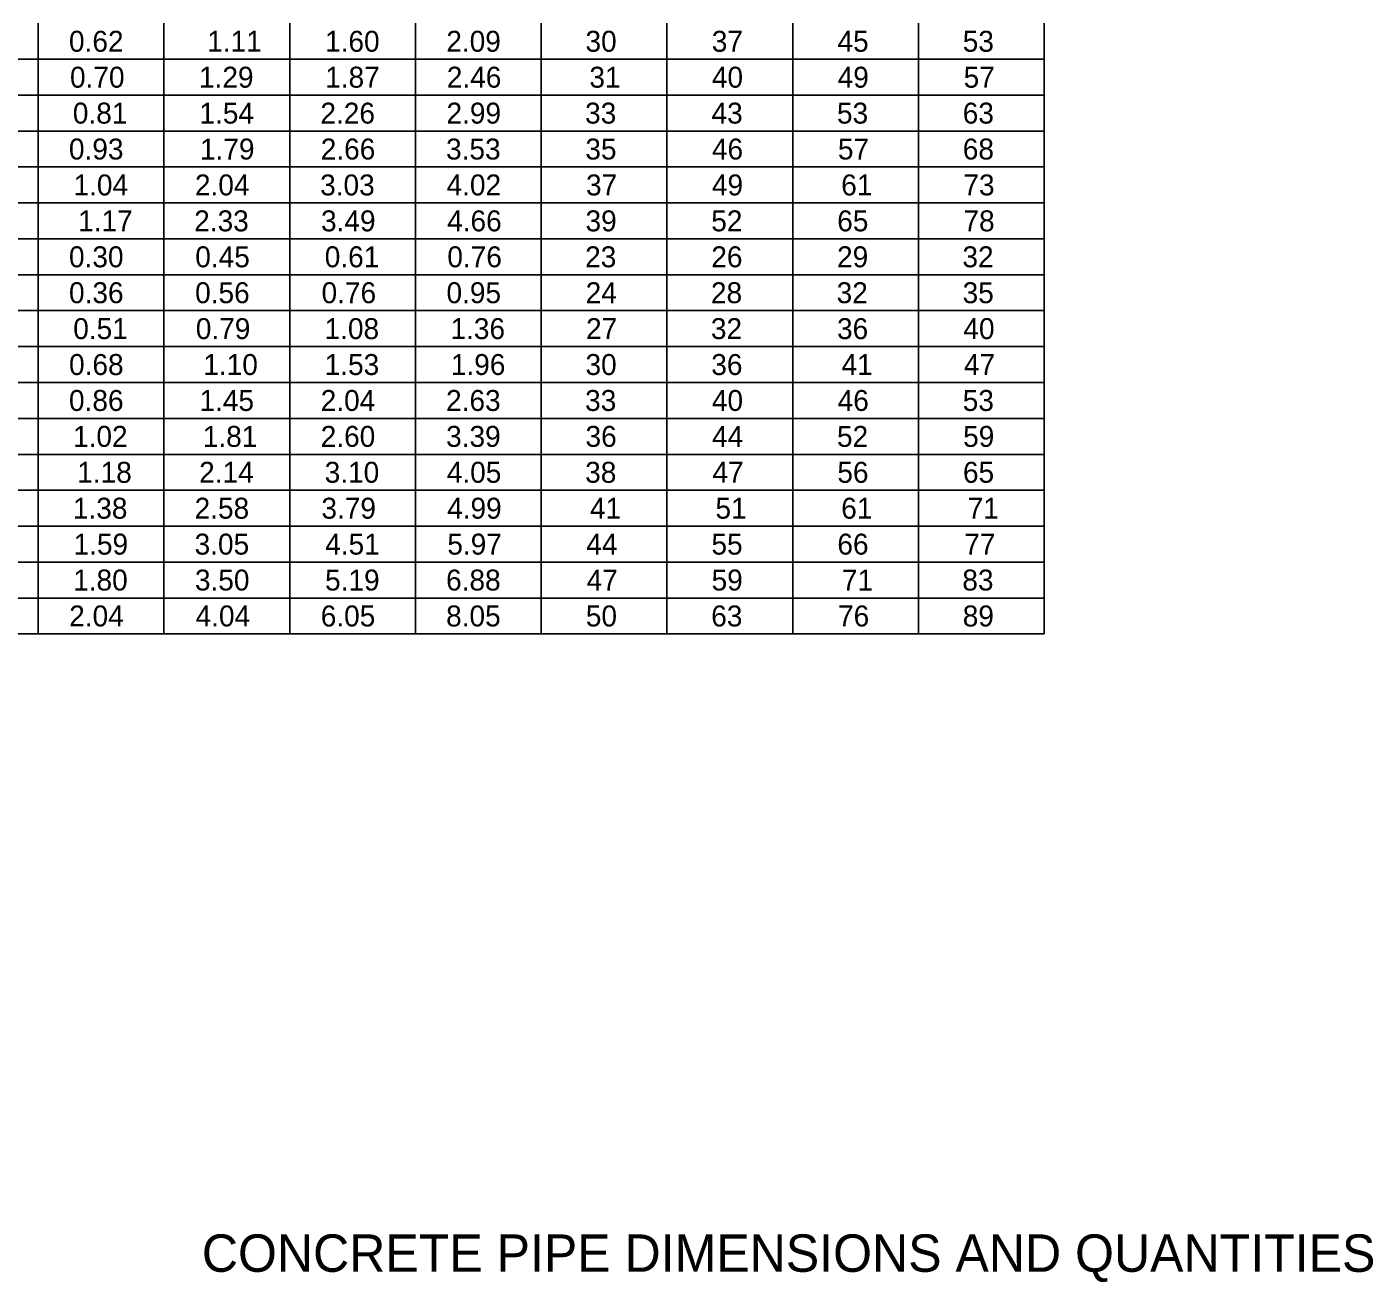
# Model space of a CAD drawing. Extents: x -1.3 to 14.6, y 0 to 8.4.
# Drawn here: x 10.062 to 14.558, y 0.024 to 4.218 of the extents above; entities that cross this region are included whole.
import ezdxf

# ---------------------------------------------------------------- set-up
doc = ezdxf.new("R2010")
doc.units = 0
doc.layers.add('Table', color=7, linetype='Continuous')
doc.layers.add('TextStructures', color=7, linetype='Continuous')

msp = doc.modelspace()

# ---------------------------------------------------------------- linework, layer by layer
at = {"layer": 'Table'}
for points in [[(10.1, 4.23), (10.1, 4.11), (10.1, 3.99), (10.1, 3.87), (10.1, 3.75), (10.1, 3.63), (10.1, 3.51), (10.1, 3.39), (10.1, 3.27), (10.1, 3.15), (10.1, 3.03), (10.1, 2.91), (10.1, 2.79), (10.1, 2.67), (10.1, 2.55), (10.1, 2.43), (10.1, 2.31), (10.1, 2.19)], [(10.52, 4.23), (10.52, 4.11), (10.52, 3.99), (10.52, 3.87), (10.52, 3.75), (10.52, 3.63), (10.52, 3.51), (10.52, 3.39), (10.52, 3.27), (10.52, 3.15), (10.52, 3.03), (10.52, 2.91), (10.52, 2.79), (10.52, 2.67), (10.52, 2.55), (10.52, 2.43), (10.52, 2.31), (10.52, 2.19)], [(10.94, 4.23), (10.94, 4.11), (10.94, 3.99), (10.94, 3.87), (10.94, 3.75), (10.94, 3.63), (10.94, 3.51), (10.94, 3.39), (10.94, 3.27), (10.94, 3.15), (10.94, 3.03), (10.94, 2.91), (10.94, 2.79), (10.94, 2.67), (10.94, 2.55), (10.94, 2.43), (10.94, 2.31), (10.94, 2.19)], [(11.36, 4.23), (11.36, 4.11), (11.36, 3.99), (11.36, 3.87), (11.36, 3.75), (11.36, 3.63), (11.36, 3.51), (11.36, 3.39), (11.36, 3.27), (11.36, 3.15), (11.36, 3.03), (11.36, 2.91), (11.36, 2.79), (11.36, 2.67), (11.36, 2.55), (11.36, 2.43), (11.36, 2.31), (11.36, 2.19)], [(11.78, 4.23), (11.78, 4.11), (11.78, 3.99), (11.78, 3.87), (11.78, 3.75), (11.78, 3.63), (11.78, 3.51), (11.78, 3.39), (11.78, 3.27), (11.78, 3.15), (11.78, 3.03), (11.78, 2.91), (11.78, 2.79), (11.78, 2.67), (11.78, 2.55), (11.78, 2.43), (11.78, 2.31), (11.78, 2.19)], [(12.2, 4.23), (12.2, 4.11), (12.2, 3.99), (12.2, 3.87), (12.2, 3.75), (12.2, 3.63), (12.2, 3.51), (12.2, 3.39), (12.2, 3.27), (12.2, 3.15), (12.2, 3.03), (12.2, 2.91), (12.2, 2.79), (12.2, 2.67), (12.2, 2.55), (12.2, 2.43), (12.2, 2.31), (12.2, 2.19)], [(12.62, 4.23), (12.62, 4.11), (12.62, 3.99), (12.62, 3.87), (12.62, 3.75), (12.62, 3.63), (12.62, 3.51), (12.62, 3.39), (12.62, 3.27), (12.62, 3.15), (12.62, 3.03), (12.62, 2.91), (12.62, 2.79), (12.62, 2.67), (12.62, 2.55), (12.62, 2.43), (12.62, 2.31), (12.62, 2.19)], [(13.04, 4.23), (13.04, 4.11), (13.04, 3.99), (13.04, 3.87), (13.04, 3.75), (13.04, 3.63), (13.04, 3.51), (13.04, 3.39), (13.04, 3.27), (13.04, 3.15), (13.04, 3.03), (13.04, 2.91), (13.04, 2.79), (13.04, 2.67), (13.04, 2.55), (13.04, 2.43), (13.04, 2.31), (13.04, 2.19)], [(13.46, 4.23), (13.46, 4.11), (13.46, 3.99), (13.46, 3.87), (13.46, 3.75), (13.46, 3.63), (13.46, 3.51), (13.46, 3.39), (13.46, 3.27), (13.46, 3.15), (13.46, 3.03), (13.46, 2.91), (13.46, 2.79), (13.46, 2.67), (13.46, 2.55), (13.46, 2.43), (13.46, 2.31), (13.46, 2.19)], [(4.04, 4.11), (4.52, 4.11), (4.94, 4.11), (5.42, 4.11), (5.66, 4.11), (6.02, 4.11), (6.38, 4.11), (6.8, 4.11), (7.22, 4.11), (7.64, 4.11), (8.06, 4.11), (8.42, 4.11), (8.84, 4.11), (9.26, 4.11), (9.68, 4.11), (10.1, 4.11), (10.52, 4.11), (10.94, 4.11), (11.36, 4.11), (11.78, 4.11), (12.2, 4.11), (12.62, 4.11), (13.04, 4.11), (13.46, 4.11)], [(4.04, 3.99), (4.52, 3.99), (4.94, 3.99), (5.42, 3.99), (5.66, 3.99), (6.02, 3.99), (6.38, 3.99), (6.8, 3.99), (7.22, 3.99), (7.64, 3.99), (8.06, 3.99), (8.42, 3.99), (8.84, 3.99), (9.26, 3.99), (9.68, 3.99), (10.1, 3.99), (10.52, 3.99), (10.94, 3.99), (11.36, 3.99), (11.78, 3.99), (12.2, 3.99), (12.62, 3.99), (13.04, 3.99), (13.46, 3.99)], [(4.04, 3.87), (4.52, 3.87), (4.94, 3.87), (5.42, 3.87), (5.66, 3.87), (6.02, 3.87), (6.38, 3.87), (6.8, 3.87), (7.22, 3.87), (7.64, 3.87), (8.06, 3.87), (8.42, 3.87), (8.84, 3.87), (9.26, 3.87), (9.68, 3.87), (10.1, 3.87), (10.52, 3.87), (10.94, 3.87), (11.36, 3.87), (11.78, 3.87), (12.2, 3.87), (12.62, 3.87), (13.04, 3.87), (13.46, 3.87)], [(4.04, 3.75), (4.52, 3.75), (4.94, 3.75), (5.42, 3.75), (5.66, 3.75), (6.02, 3.75), (6.38, 3.75), (6.8, 3.75), (7.22, 3.75), (7.64, 3.75), (8.06, 3.75), (8.42, 3.75), (8.84, 3.75), (9.26, 3.75), (9.68, 3.75), (10.1, 3.75), (10.52, 3.75), (10.94, 3.75), (11.36, 3.75), (11.78, 3.75), (12.2, 3.75), (12.62, 3.75), (13.04, 3.75), (13.46, 3.75)], [(4.04, 3.63), (4.52, 3.63), (4.94, 3.63), (5.42, 3.63), (5.66, 3.63), (6.02, 3.63), (6.38, 3.63), (6.8, 3.63), (7.22, 3.63), (7.64, 3.63), (8.06, 3.63), (8.42, 3.63), (8.84, 3.63), (9.26, 3.63), (9.68, 3.63), (10.1, 3.63), (10.52, 3.63), (10.94, 3.63), (11.36, 3.63), (11.78, 3.63), (12.2, 3.63), (12.62, 3.63), (13.04, 3.63), (13.46, 3.63)], [(4.04, 3.51), (4.52, 3.51), (4.94, 3.51), (5.42, 3.51), (5.66, 3.51), (6.02, 3.51), (6.38, 3.51), (6.8, 3.51), (7.22, 3.51), (7.64, 3.51), (8.06, 3.51), (8.42, 3.51), (8.84, 3.51), (9.26, 3.51), (9.68, 3.51), (10.1, 3.51), (10.52, 3.51), (10.94, 3.51), (11.36, 3.51), (11.78, 3.51), (12.2, 3.51), (12.62, 3.51), (13.04, 3.51), (13.46, 3.51)], [(4.04, 3.39), (4.52, 3.39), (4.94, 3.39), (5.42, 3.39), (5.66, 3.39), (6.02, 3.39), (6.38, 3.39), (6.8, 3.39), (7.22, 3.39), (7.64, 3.39), (8.06, 3.39), (8.42, 3.39), (8.84, 3.39), (9.26, 3.39), (9.68, 3.39), (10.1, 3.39), (10.52, 3.39), (10.94, 3.39), (11.36, 3.39), (11.78, 3.39), (12.2, 3.39), (12.62, 3.39), (13.04, 3.39), (13.46, 3.39)], [(4.04, 3.27), (4.52, 3.27), (4.94, 3.27), (5.42, 3.27), (5.66, 3.27), (6.02, 3.27), (6.38, 3.27), (6.8, 3.27), (7.22, 3.27), (7.64, 3.27), (8.06, 3.27), (8.42, 3.27), (8.84, 3.27), (9.26, 3.27), (9.68, 3.27), (10.1, 3.27), (10.52, 3.27), (10.94, 3.27), (11.36, 3.27), (11.78, 3.27), (12.2, 3.27), (12.62, 3.27), (13.04, 3.27), (13.46, 3.27)], [(4.04, 3.15), (4.52, 3.15), (4.94, 3.15), (5.42, 3.15), (5.66, 3.15), (6.02, 3.15), (6.38, 3.15), (6.8, 3.15), (7.22, 3.15), (7.64, 3.15), (8.06, 3.15), (8.42, 3.15), (8.84, 3.15), (9.26, 3.15), (9.68, 3.15), (10.1, 3.15), (10.52, 3.15), (10.94, 3.15), (11.36, 3.15), (11.78, 3.15), (12.2, 3.15), (12.62, 3.15), (13.04, 3.15), (13.46, 3.15)], [(4.04, 3.03), (4.52, 3.03), (4.94, 3.03), (5.42, 3.03), (5.66, 3.03), (6.02, 3.03), (6.38, 3.03), (6.8, 3.03), (7.22, 3.03), (7.64, 3.03), (8.06, 3.03), (8.42, 3.03), (8.84, 3.03), (9.26, 3.03), (9.68, 3.03), (10.1, 3.03), (10.52, 3.03), (10.94, 3.03), (11.36, 3.03), (11.78, 3.03), (12.2, 3.03), (12.62, 3.03), (13.04, 3.03), (13.46, 3.03)], [(4.04, 2.91), (4.52, 2.91), (4.94, 2.91), (5.42, 2.91), (5.66, 2.91), (6.02, 2.91), (6.38, 2.91), (6.8, 2.91), (7.22, 2.91), (7.64, 2.91), (8.06, 2.91), (8.42, 2.91), (8.84, 2.91), (9.26, 2.91), (9.68, 2.91), (10.1, 2.91), (10.52, 2.91), (10.94, 2.91), (11.36, 2.91), (11.78, 2.91), (12.2, 2.91), (12.62, 2.91), (13.04, 2.91), (13.46, 2.91)], [(4.04, 2.79), (4.52, 2.79), (4.94, 2.79), (5.42, 2.79), (5.66, 2.79), (6.02, 2.79), (6.38, 2.79), (6.8, 2.79), (7.22, 2.79), (7.64, 2.79), (8.06, 2.79), (8.42, 2.79), (8.84, 2.79), (9.26, 2.79), (9.68, 2.79), (10.1, 2.79), (10.52, 2.79), (10.94, 2.79), (11.36, 2.79), (11.78, 2.79), (12.2, 2.79), (12.62, 2.79), (13.04, 2.79), (13.46, 2.79)], [(4.04, 2.67), (4.52, 2.67), (4.94, 2.67), (5.42, 2.67), (5.66, 2.67), (6.02, 2.67), (6.38, 2.67), (6.8, 2.67), (7.22, 2.67), (7.64, 2.67), (8.06, 2.67), (8.42, 2.67), (8.84, 2.67), (9.26, 2.67), (9.68, 2.67), (10.1, 2.67), (10.52, 2.67), (10.94, 2.67), (11.36, 2.67), (11.78, 2.67), (12.2, 2.67), (12.62, 2.67), (13.04, 2.67), (13.46, 2.67)], [(4.04, 2.55), (4.52, 2.55), (4.94, 2.55), (5.42, 2.55), (5.66, 2.55), (6.02, 2.55), (6.38, 2.55), (6.8, 2.55), (7.22, 2.55), (7.64, 2.55), (8.06, 2.55), (8.42, 2.55), (8.84, 2.55), (9.26, 2.55), (9.68, 2.55), (10.1, 2.55), (10.52, 2.55), (10.94, 2.55), (11.36, 2.55), (11.78, 2.55), (12.2, 2.55), (12.62, 2.55), (13.04, 2.55), (13.46, 2.55)], [(4.04, 2.43), (4.52, 2.43), (4.94, 2.43), (5.42, 2.43), (5.66, 2.43), (6.02, 2.43), (6.38, 2.43), (6.8, 2.43), (7.22, 2.43), (7.64, 2.43), (8.06, 2.43), (8.42, 2.43), (8.84, 2.43), (9.26, 2.43), (9.68, 2.43), (10.1, 2.43), (10.52, 2.43), (10.94, 2.43), (11.36, 2.43), (11.78, 2.43), (12.2, 2.43), (12.62, 2.43), (13.04, 2.43), (13.46, 2.43)], [(4.04, 2.31), (4.52, 2.31), (4.94, 2.31), (5.42, 2.31), (5.66, 2.31), (6.02, 2.31), (6.38, 2.31), (6.8, 2.31), (7.22, 2.31), (7.64, 2.31), (8.06, 2.31), (8.42, 2.31), (8.84, 2.31), (9.26, 2.31), (9.68, 2.31), (10.1, 2.31), (10.52, 2.31), (10.94, 2.31), (11.36, 2.31), (11.78, 2.31), (12.2, 2.31), (12.62, 2.31), (13.04, 2.31), (13.46, 2.31)], [(4.04, 2.19), (4.52, 2.19), (4.94, 2.19), (5.42, 2.19), (5.66, 2.19), (6.02, 2.19), (6.38, 2.19), (6.8, 2.19), (7.22, 2.19), (7.64, 2.19), (8.06, 2.19), (8.42, 2.19), (8.84, 2.19), (9.26, 2.19), (9.68, 2.19), (10.1, 2.19), (10.52, 2.19), (10.94, 2.19), (11.36, 2.19), (11.78, 2.19), (12.2, 2.19), (12.62, 2.19), (13.04, 2.19), (13.46, 2.19)]]:
    msp.add_lwpolyline(points, dxfattribs=at)

# ---------------------------------------------------------------- texts
for s, p in [('0.62', (10.2029, 4.135)), ('1.11', (10.6645, 4.135)), ('1.60', (11.0581, 4.135)), ('2.09', (11.4631, 4.135)), ('0.70', (10.2063, 4.015)), ('1.29', (10.6371, 4.015)), ('1.87', (11.0586, 4.015)), ('2.46', (11.4647, 4.015)), ('0.81', (10.2158, 3.895)), ('1.54', (10.6386, 3.895)), ('2.26', (11.0426, 3.895)), ('2.99', (11.4637, 3.895)), ('0.93', (10.2028, 3.775)), ('1.79', (10.6404, 3.775)), ('2.66', (11.0437, 3.775)), ('3.53', (11.4622, 3.775)), ('1.04', (10.2181, 3.655)), ('2.04', (10.6236, 3.655)), ('3.03', (11.0417, 3.655)), ('4.02', (11.4639, 3.655)), ('1.17', (10.2334, 3.535)), ('2.33', (10.6211, 3.535)), ('3.49', (11.0446, 3.535)), ('4.66', (11.4658, 3.535)), ('0.30', (10.2029, 3.415)), ('0.45', (10.6247, 3.415)), ('0.61', (11.0571, 3.415)), ('0.76', (11.4665, 3.415)), ('0.36', (10.203, 3.295)), ('0.56', (10.6242, 3.295)), ('0.76', (11.0465, 3.295)), ('0.95', (11.4637, 3.295)), ('0.51', (10.2171, 3.175)), ('0.79', (10.6265, 3.175)), ('1.08', (11.0565, 3.175)), ('1.36', (11.477, 3.175)), ('0.68', (10.2031, 3.055)), ('1.10', (10.6515, 3.055)), ('1.53', (11.0568, 3.055)), ('1.96', (11.4782, 3.055)), ('0.86', (10.2029, 2.935)), ('1.45', (10.6387, 2.935)), ('2.04', (11.0436, 2.935)), ('2.63', (11.4623, 2.935)), ('1.02', (10.2164, 2.815)), ('1.81', (10.6498, 2.815)), ('2.60', (11.0436, 2.815)), ('3.39', (11.4624, 2.815)), ('1.18', (10.2305, 2.695)), ('2.14', (10.6376, 2.695)), ('3.10', (11.0569, 2.695)), ('4.05', (11.4647, 2.695)), ('1.38', (10.2159, 2.575)), ('2.58', (10.6225, 2.575)), ('3.79', (11.0459, 2.575)), ('4.99', (11.4658, 2.575)), ('1.59', (10.2182, 2.455)), ('3.05', (10.6225, 2.455)), ('4.51', (11.0586, 2.455)), ('5.97', (11.4665, 2.455)), ('1.80', (10.2168, 2.335)), ('3.50', (10.6235, 2.335)), ('5.19', (11.0582, 2.335)), ('6.88', (11.4623, 2.335)), ('2.04', (10.2036, 2.215)), ('4.04', (10.6257, 2.215)), ('6.05', (11.0437, 2.215)), ('8.05', (11.4624, 2.215))]:
    msp.add_text(s, height=0.07, dxfattribs=at).set_placement(p)
for s, p in [('30', (11.9279, 4.135)), ('37', (12.3497, 4.135)), ('45', (12.7696, 4.135)), ('53', (13.1878, 4.135)), ('31', (11.9409, 4.015)), ('40', (12.35, 4.015)), ('49', (12.7701, 4.015)), ('57', (13.1909, 4.015)), ('33', (11.9266, 3.895)), ('43', (12.3488, 3.895)), ('53', (12.7678, 3.895)), ('63', (13.1878, 3.895)), ('35', (11.9274, 3.775)), ('46', (12.3501, 3.775)), ('57', (12.7709, 3.775)), ('68', (13.188, 3.775)), ('37', (11.9297, 3.655)), ('49', (12.3501, 3.655)), ('61', (12.782, 3.655)), ('73', (13.19, 3.655)), ('39', (11.928, 3.535)), ('52', (12.3479, 3.535)), ('65', (12.7686, 3.535)), ('78', (13.1902, 3.535)), ('23', (11.9267, 3.415)), ('26', (12.3481, 3.415)), ('29', (12.7681, 3.415)), ('32', (13.1867, 3.415)), ('24', (11.9285, 3.295)), ('28', (12.3469, 3.295)), ('32', (12.7667, 3.295)), ('35', (13.1874, 3.295)), ('27', (11.9298, 3.175)), ('32', (12.3467, 3.175)), ('36', (12.768, 3.175)), ('40', (13.19, 3.175)), ('30', (11.9279, 3.055)), ('36', (12.348, 3.055)), ('41', (12.783, 3.055)), ('47', (13.1919, 3.055)), ('33', (11.9266, 2.935)), ('40', (12.35, 2.935)), ('46', (12.7701, 2.935)), ('53', (13.1878, 2.935)), ('36', (11.928, 2.815)), ('44', (12.3506, 2.815)), ('52', (12.7679, 2.815)), ('59', (13.1891, 2.815)), ('38', (11.9268, 2.695)), ('47', (12.3519, 2.695)), ('56', (12.7691, 2.695)), ('65', (13.1886, 2.695)), ('41', (11.943, 2.575)), ('51', (12.362, 2.575)), ('61', (12.782, 2.575)), ('71', (13.2043, 2.575)), ('44', (11.9306, 2.455)), ('55', (12.3486, 2.455)), ('66', (12.7691, 2.455)), ('77', (13.1931, 2.455)), ('47', (11.9319, 2.335)), ('59', (12.3491, 2.335)), ('71', (12.7843, 2.335)), ('83', (13.1865, 2.335)), ('50', (11.929, 2.215)), ('63', (12.3478, 2.215)), ('76', (12.7714, 2.215)), ('89', (13.1878, 2.215))]:
    msp.add_text(s, height=0.07, rotation=0, dxfattribs=at).set_placement(p)
at = {"layer": 'TextStructures'}
msp.add_text('CONCRETE PIPE DIMENSIONS AND QUANTITIES', height=0.125, rotation=0, dxfattribs=at).set_placement((10.6466, 0.0588))

doc.saveas('drawing.dxf')
